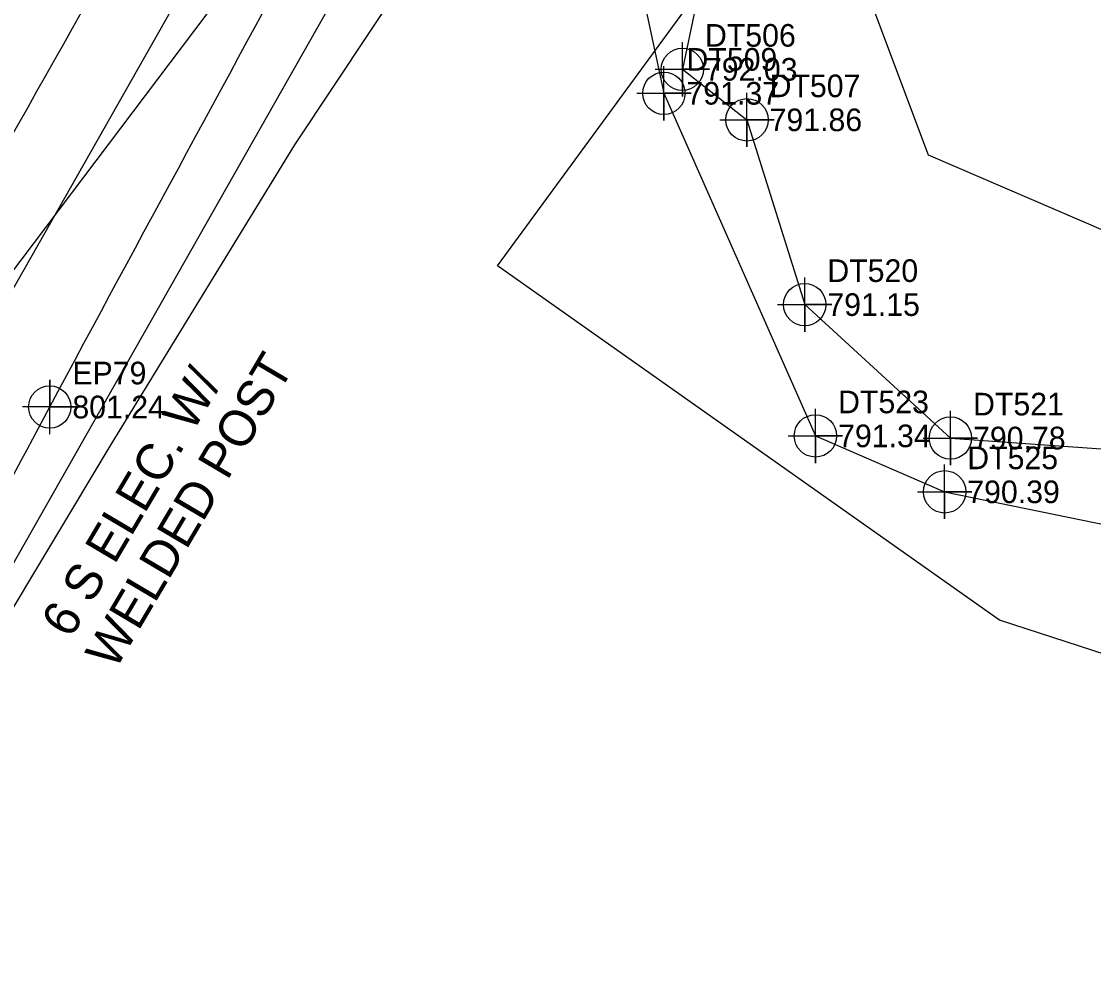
# Model space of a CAD drawing. Extents: x 1316460 to 1321645, y 684173 to 687077.
# Drawn here: x 1319254 to 1319372.4, y 685478.8 to 685583.2 of the extents above; entities that cross this region are included whole.
import ezdxf

# ---------------------------------------------------------------- set-up
doc = ezdxf.new("R2010")
doc.units = 0
for name, color, linetype in [('CTL Supplemental Horizontal and Vertical Cogo Elevation', 7, 'Continuous'), ('Exist Horizontal Alignment', 7, 'Continuous'), ('Exist Horizontal Baseline Alignment', 7, 'Continuous'), ('Exist Hydro Stream or Body of Water Cogo Elevation', 7, 'Continuous'), ('Exist Hydro Stream or Body of Water Cogo Number', 7, 'Continuous'), ('Exist Hydro Stream or Body of Water Cogo Point CELL', 7, 'Continuous'), ('Exist Hydrographic Top of Bank Cogo Number', 7, 'Continuous'), ('Exist Hydrographic Top of Bank Cogo Point CELL', 7, 'Continuous'), ('Exist Hydrographic Water Edge Cogo Elevation', 7, 'Continuous'), ('Exist Hydrographic Water Surface Cogo Number', 7, 'Continuous'), ('Exist Other Culture Fence Line', 7, 'Continuous'), ('Exist Other Culture Fence Line Text', 7, 'Continuous'), ('Exist Right of Way Line', 7, 'Continuous'), ('Exist Vegetation Woods Line', 7, 'Continuous')]:
    doc.layers.add(name, color=color, linetype=linetype)

msp = doc.modelspace()

# ---------------------------------------------------------------- linework, layer by layer
at = {"layer": 'CTL Supplemental Horizontal and Vertical Cogo Elevation'}
msp.add_lwpolyline([(1319257.11, 685537.59), (1319257.11, 685543.59), (1319257.11, 685540.59), (1319260.11, 685540.59), (1319254.11, 685540.59)], dxfattribs=at)
msp.add_circle((1319257.11, 685540.59), 2.34, dxfattribs=at)
at = {"layer": 'Exist Horizontal Alignment'}
msp.add_line((1319222.92, 685500.58), (1319275.11, 685592.51), dxfattribs=at)
at = {"layer": 'Exist Horizontal Baseline Alignment'}
msp.add_line((1319075.82, 685321.04), (1319324.12, 685649.7), dxfattribs=at)
at = {"layer": 'Exist Hydro Stream or Body of Water Cogo Point CELL'}
for points in [[(1319324, 685577.89), (1319330, 685577.89), (1319327, 685577.89), (1319327, 685574.89), (1319327, 685580.89)], [(1319321.96, 685575.24), (1319327.96, 685575.24), (1319324.96, 685575.24), (1319324.96, 685572.24), (1319324.96, 685578.24)], [(1319331.14, 685572.31), (1319337.14, 685572.31), (1319334.14, 685572.31), (1319334.14, 685569.31), (1319334.14, 685575.31)], [(1319337.52, 685551.9), (1319343.52, 685551.9), (1319340.52, 685551.9), (1319340.52, 685548.9), (1319340.52, 685554.9)], [(1319338.71, 685537.4), (1319344.71, 685537.4), (1319341.71, 685537.4), (1319341.71, 685534.4), (1319341.71, 685540.4)], [(1319353.62, 685537.16), (1319359.62, 685537.16), (1319356.62, 685537.16), (1319356.62, 685534.16), (1319356.62, 685540.16)], [(1319352.98, 685531.22), (1319358.98, 685531.22), (1319355.98, 685531.22), (1319355.98, 685528.22), (1319355.98, 685534.22)]]:
    msp.add_lwpolyline(points, dxfattribs=at)
for centre in [(1319327, 685577.89), (1319324.96, 685575.24), (1319334.14, 685572.31), (1319340.52, 685551.9), (1319341.71, 685537.4), (1319356.62, 685537.16), (1319355.98, 685531.22)]:
    msp.add_circle(centre, 2.34, dxfattribs=at)
at = {"layer": 'Exist Hydrographic Water Edge Cogo Elevation'}
for points in [[(1319315.39, 685642.15), (1319316.13, 685639.47), (1319321.51, 685617.26), (1319325.54, 685603.7), (1319328.94, 685587.06), (1319327, 685577.89), (1319334.14, 685572.31), (1319340.52, 685551.9), (1319356.62, 685537.16), (1319376.4, 685535.73), (1319409.06, 685526.08), (1319419.9, 685532.1), (1319428.67, 685524.94), (1319444.12, 685513.41), (1319467.2, 685502.53), (1319480.5, 685494.41), (1319522.69, 685482.44), (1319536.76, 685479.18), (1319552.73, 685463.94), (1319556.78, 685445.44), (1319572.32, 685412.25), (1319579.73, 685410.53), (1319583.37, 685414.31), (1319593.53, 685423.25)], [(1319307.41, 685629.09), (1319308.12, 685625.61), (1319313.96, 685605.72), (1319322.55, 685586.43), (1319324.96, 685575.24), (1319341.71, 685537.4), (1319355.98, 685531.22), (1319377.19, 685526.88), (1319408.85, 685522.51), (1319422.93, 685520.07), (1319440.06, 685507.64), (1319462.81, 685492.01), (1319478.25, 685487.57), (1319521.18, 685478.7), (1319540.16, 685466.17), (1319547.99, 685448.35)]]:
    msp.add_lwpolyline(points, dxfattribs=at)
at = {"layer": 'Exist Hydrographic Water Surface Cogo Number'}
for points in [[(1319055.19, 685337.87), (1319087.61, 685357.9), (1319111.37, 685376.19), (1319141.98, 685405.77), (1319163.7, 685432.36), (1319194.31, 685473.2), (1319218.75, 685514.19), (1319240.59, 685549.48), (1319272.58, 685605.07), (1319285.11, 685625.97)], [(1319062.61, 685318.94), (1319095.65, 685339.51), (1319123.83, 685361.21), (1319155.56, 685391.6), (1319180.39, 685419.44), (1319210.73, 685463.75), (1319236.48, 685503.5), (1319257.11, 685540.59), (1319287.5, 685596.76)]]:
    msp.add_spline(points, degree=3, dxfattribs=at)
at = {"layer": 'Exist Other Culture Fence Line'}
msp.add_lwpolyline([(1319190.99, 685412.25), (1319193.61, 685416), (1319211.36, 685446.63), (1319232.44, 685483.68), (1319244.86, 685504.76), (1319263.9, 685536.45), (1319284.2, 685569.54), (1319300.91, 685594.72), (1319314.93, 685591.93), (1319333.05, 685589.55), (1319337.98, 685607.09)], dxfattribs=at)
at = {"layer": 'Exist Right of Way Line'}
msp.add_line((1319235.97, 685493.18), (1319288.16, 685585.1), dxfattribs=at)
at = {"layer": 'Exist Vegetation Woods Line'}
msp.add_lwpolyline([(1319431.49, 685494.46), (1319362.05, 685517.04), (1319306.58, 685556.19), (1319341.07, 685603.33), (1319354.17, 685568.45), (1319387.8, 685553.99), (1319409.91, 685562.52), (1319431.79, 685558.86)], dxfattribs=at)

# ---------------------------------------------------------------- texts
at = {"layer": 'Exist Hydro Stream or Body of Water Cogo Elevation'}
for s, p in [('792.03', (1319329.5, 685576.64)), ('791.37', (1319327.46, 685573.99)), ('791.86', (1319336.64, 685571.06)), ('791.15', (1319343.02, 685550.65)), ('791.34', (1319344.21, 685536.15)), ('790.78', (1319359.12, 685535.91)), ('790.39', (1319358.48, 685529.97))]:
    msp.add_text(s, height=2.5, dxfattribs=at).set_placement(p)
at = {"layer": 'Exist Hydro Stream or Body of Water Cogo Number'}
for s, p in [('DT506', (1319329.5, 685580.39)), ('DT509', (1319327.46, 685577.74)), ('DT507', (1319336.64, 685574.81)), ('DT520', (1319343.02, 685554.4)), ('DT523', (1319344.21, 685539.9)), ('DT521', (1319359.12, 685539.66)), ('DT525', (1319358.48, 685533.72))]:
    msp.add_text(s, height=2.5, dxfattribs=at).set_placement(p)
at = {"layer": 'Exist Hydrographic Top of Bank Cogo Number'}
msp.add_text('801.24', height=2.5, dxfattribs=at).set_placement((1319259.61, 685539.34))
at = {"layer": 'Exist Hydrographic Top of Bank Cogo Point CELL'}
msp.add_text('EP79', height=2.5, dxfattribs=at).set_placement((1319259.61, 685543.09))
at = {"layer": 'Exist Other Culture Fence Line Text'}
for s, p in [(' WELDED POST', (1319263.57, 685510.13)), ('6 S ELEC. W/', (1319259.42, 685514.9))]:
    msp.add_text(s, height=4, rotation=59.4265, dxfattribs=at).set_placement(p)

doc.saveas('drawing.dxf')
